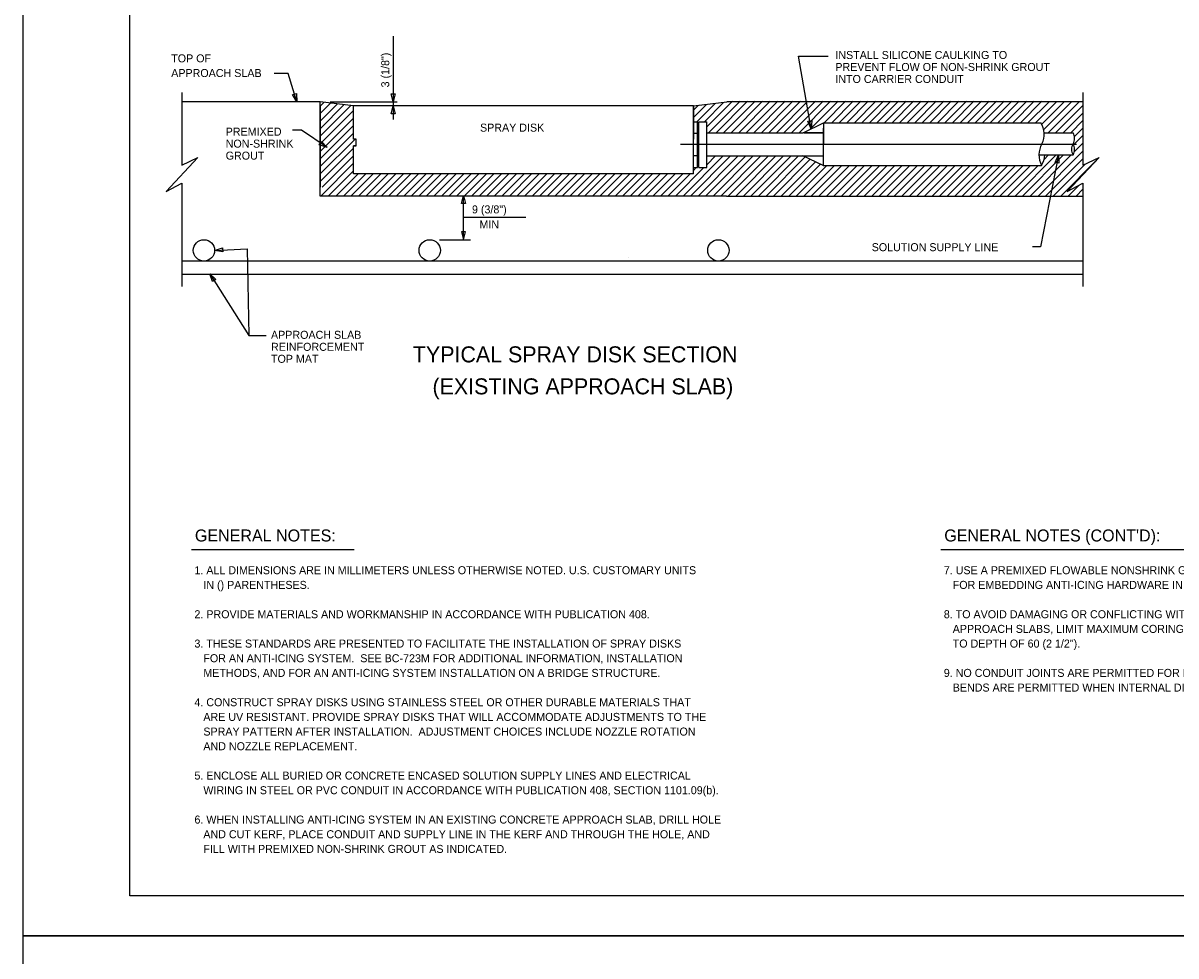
# Model space of a CAD drawing. Extents: x 3239 to 4230, y -4276 to -2494.
# Drawn here: x 3239 to 3671.4, y -3095.8 to -2746 of the extents above; entities that cross this region are included whole.
import ezdxf

# ---------------------------------------------------------------- set-up
doc = ezdxf.new("R2010")
doc.units = 0
doc.layers.add('2', color=7, linetype='Continuous')
doc.layers.add('PLT-BNDY', color=7, linetype='Continuous')

msp = doc.modelspace()

# ---------------------------------------------------------------- linework, layer by layer
at = {"layer": '2'}
for p, q in [((3279.03, -3073.29), (3279.03, -2509.29)), ((3377.84, -2750.85), (3377.84, -2782.13)), ((3338.44, -2764.84), (3333.2, -2764.84)), ((3341.71, -2775.45), (3338.44, -2764.84)), ((3298.57, -2772.06), (3298.57, -2799.29)), ((3350.43, -2775.45), (3298.57, -2775.45)), ((3362.93, -2776.95), (3350.43, -2775.45)), ((3350.43, -2810.82), (3350.43, -2775.45)), ((3354.22, -2775.45), (3379.34, -2775.45)), ((3490.43, -2776.95), (3502.93, -2775.45)), ((3495.43, -2784.92), (3505.05, -2775.29)), ((3496.07, -2787.11), (3507.88, -2775.29)), ((3498.9, -2787.11), (3510.71, -2775.29)), ((3501.73, -2787.11), (3513.54, -2775.29)), ((3636.47, -2775.45), (3502.93, -2775.45)), ((3504.56, -2787.11), (3516.37, -2775.29)), ((3507.39, -2787.11), (3519.2, -2775.29)), ((3510.22, -2787.11), (3522.03, -2775.29)), ((3513.05, -2787.11), (3524.86, -2775.29)), ((3515.88, -2787.11), (3527.69, -2775.29)), ((3518.71, -2787.11), (3530.52, -2775.29)), ((3521.54, -2787.11), (3533.35, -2775.29)), ((3524.37, -2787.11), (3536.18, -2775.29)), ((3527.2, -2787.11), (3539.01, -2775.29)), ((3530.03, -2787.11), (3541.84, -2775.29)), ((3534.18, -2785.79), (3544.67, -2775.29)), ((3539.44, -2783.35), (3547.5, -2775.29)), ((3542.27, -2783.35), (3550.33, -2775.29)), ((3545.1, -2783.35), (3553.16, -2775.29)), ((3547.93, -2783.35), (3555.99, -2775.29)), ((3550.76, -2783.35), (3558.82, -2775.29)), ((3553.59, -2783.35), (3561.65, -2775.29)), ((3556.42, -2783.35), (3564.48, -2775.29)), ((3559.25, -2783.35), (3567.31, -2775.29)), ((3562.08, -2783.35), (3570.14, -2775.29)), ((3564.91, -2783.35), (3572.97, -2775.29)), ((3567.74, -2783.35), (3575.8, -2775.29)), ((3570.57, -2783.35), (3578.63, -2775.29)), ((3573.4, -2783.35), (3581.46, -2775.29)), ((3576.23, -2783.35), (3584.29, -2775.29)), ((3579.06, -2783.35), (3587.12, -2775.29)), ((3581.89, -2783.35), (3589.95, -2775.29)), ((3584.72, -2783.35), (3592.78, -2775.29)), ((3587.55, -2783.35), (3595.61, -2775.29)), ((3590.38, -2783.35), (3598.44, -2775.29)), ((3593.21, -2783.35), (3601.27, -2775.29)), ((3596.04, -2783.35), (3604.1, -2775.29)), ((3598.87, -2783.35), (3606.93, -2775.29)), ((3601.7, -2783.35), (3609.76, -2775.29)), ((3604.53, -2783.35), (3612.59, -2775.29)), ((3607.36, -2783.35), (3615.42, -2775.29)), ((3610.19, -2783.35), (3618.25, -2775.29)), ((3613.02, -2783.35), (3621.08, -2775.29)), ((3615.85, -2783.35), (3623.76, -2775.45)), ((3618.68, -2783.35), (3626.59, -2775.45)), ((3621.02, -2783.84), (3629.42, -2775.45)), ((3621.79, -2785.89), (3632.24, -2775.45)), ((3623.4, -2787.12), (3635.07, -2775.45)), ((3636.47, -2772.06), (3636.47, -2799.29)), ((3350.43, -2777.1), (3351.9, -2775.62)), ((3350.43, -2779.93), (3354.43, -2775.93)), ((3350.43, -2782.75), (3356.95, -2776.23)), ((3350.43, -2785.58), (3359.48, -2776.53)), ((3350.43, -2788.41), (3362, -2776.83)), ((3350.43, -2776.95), (3350.43, -2807.45)), ((3350.43, -2791.24), (3362.93, -2778.74)), ((3362.93, -2789.45), (3362.93, -2776.95)), ((3362.93, -2789.45), (3362.93, -2776.95)), ((3490.43, -2776.95), (3362.93, -2776.95)), ((3490.43, -2781.43), (3495.3, -2776.55)), ((3490.43, -2778.58), (3492.28, -2776.72)), ((3490.43, -2789.45), (3490.43, -2776.95)), ((3490.43, -2776.95), (3490.43, -2789.45)), ((3491.74, -2782.95), (3498.52, -2776.16)), ((3494.57, -2782.95), (3501.74, -2775.78)), ((3626.23, -2787.12), (3636.47, -2776.87)), ((3629.05, -2787.12), (3636.47, -2779.7)), ((3350.43, -2794.07), (3362.93, -2781.57)), ((3490.43, -2782.95), (3491.92, -2782.95)), ((3491.92, -2800.19), (3491.92, -2782.95)), ((3492.42, -2800.19), (3492.42, -2782.95)), ((3492.42, -2782.95), (3495.43, -2782.95)), ((3495.43, -2800.19), (3495.43, -2782.95)), ((3539.13, -2783.57), (3539.12, -2799.32)), ((3539.13, -2783.35), (3620.73, -2783.35)), ((3631.88, -2787.12), (3636.47, -2782.53)), ((3343.4, -2786.1), (3340.03, -2786.1)), ((3353.01, -2792.68), (3343.4, -2786.1)), ((3350.43, -2796.9), (3362.93, -2784.4)), ((3350.43, -2799.72), (3362.93, -2787.22)), ((3490.43, -2787.3), (3491.92, -2787.3)), ((3495.43, -2797.45), (3495.43, -2785.45)), ((3495.43, -2787.11), (3531.52, -2787.11)), ((3531.92, -2787.11), (3539.12, -2787.11)), ((3539.12, -2787.11), (3539.12, -2795.78)), ((3539.14, -2791.89), (3539.13, -2788.2)), ((3621.97, -2787.12), (3632.77, -2787.12)), ((3632.98, -2791.68), (3636.47, -2788.18)), ((3633.28, -2788.55), (3636.47, -2785.35)), ((3350.43, -2802.55), (3363.53, -2789.45)), ((3363.93, -2789.45), (3362.93, -2789.45)), ((3363.93, -2789.45), (3362.93, -2789.45)), ((3363.93, -2791.95), (3362.93, -2791.95)), ((3362.93, -2802.45), (3362.93, -2791.95)), ((3362.93, -2795.95), (3362.93, -2791.95)), ((3362.93, -2791.95), (3363.93, -2791.95)), ((3363.93, -2791.95), (3363.93, -2789.45)), ((3363.93, -2791.95), (3363.93, -2789.45)), ((3608.55, -2791.45), (3485.58, -2791.45)), ((3490.43, -2802.45), (3490.43, -2789.45)), ((3634.08, -2791.45), (3608.55, -2791.45)), ((3633.23, -2794.25), (3636.47, -2791.01)), ((3304.6, -2796.39), (3292.7, -2809.17)), ((3298.57, -2799.29), (3304.6, -2796.39)), ((3350.43, -2805.38), (3362.93, -2792.88)), ((3351.19, -2807.45), (3362.69, -2795.95)), ((3486.51, -2810.82), (3501.54, -2795.78)), ((3489.34, -2810.82), (3504.37, -2795.78)), ((3490.43, -2795.6), (3491.92, -2795.6)), ((3492.17, -2810.82), (3507.2, -2795.78)), ((3495, -2810.82), (3510.03, -2795.78)), ((3495.43, -2795.78), (3531.49, -2795.78)), ((3495.43, -2799.07), (3498.71, -2795.78)), ((3497.83, -2810.82), (3512.86, -2795.78)), ((3500.66, -2810.82), (3515.69, -2795.78)), ((3503.49, -2810.82), (3518.52, -2795.78)), ((3506.32, -2810.82), (3521.35, -2795.78)), ((3509.15, -2810.82), (3524.18, -2795.78)), ((3511.98, -2810.82), (3527.01, -2795.78)), ((3514.81, -2810.82), (3529.84, -2795.78)), ((3517.64, -2810.82), (3532.3, -2796.16)), ((3520.47, -2810.82), (3534.23, -2797.05)), ((3531.92, -2795.78), (3539.12, -2795.78)), ((3611.01, -2810.82), (3626.4, -2795.43)), ((3613.84, -2810.82), (3629.23, -2795.43)), ((3616.67, -2810.82), (3632.05, -2795.43)), ((3619.65, -2810.82), (3636.47, -2793.99)), ((3619.96, -2795.43), (3632.77, -2795.43)), ((3621.9, -2797.1), (3623.57, -2795.43)), ((3622.47, -2810.82), (3636.47, -2796.82)), ((3628.13, -2810.82), (3641.79, -2797.16)), ((3642.51, -2796.39), (3630.6, -2809.17)), ((3636.47, -2799.29), (3642.51, -2796.39)), ((3350.65, -2810.82), (3362.93, -2798.54)), ((3353.48, -2810.82), (3362.93, -2801.37)), ((3483.68, -2810.82), (3494.3, -2800.19)), ((3490.43, -2800.19), (3491.92, -2800.19)), ((3490.43, -2801.24), (3491.47, -2800.19)), ((3492.42, -2800.19), (3495.43, -2800.19)), ((3523.3, -2810.82), (3536.16, -2797.95)), ((3526.13, -2810.82), (3538.09, -2798.85)), ((3528.96, -2810.82), (3540.45, -2799.32)), ((3531.79, -2810.82), (3543.28, -2799.32)), ((3534.62, -2810.82), (3546.11, -2799.32)), ((3537.45, -2810.82), (3548.94, -2799.32)), ((3539.12, -2799.32), (3620.98, -2799.32)), ((3540.28, -2810.82), (3551.77, -2799.32)), ((3543.11, -2810.82), (3554.6, -2799.32)), ((3545.94, -2810.82), (3557.43, -2799.32)), ((3548.77, -2810.82), (3560.26, -2799.32)), ((3551.6, -2810.82), (3563.09, -2799.32)), ((3554.43, -2810.82), (3565.92, -2799.32)), ((3557.26, -2810.82), (3568.75, -2799.32)), ((3560.09, -2810.82), (3571.58, -2799.32)), ((3562.92, -2810.82), (3574.41, -2799.32)), ((3565.75, -2810.82), (3577.24, -2799.32)), ((3568.58, -2810.82), (3580.07, -2799.32)), ((3571.41, -2810.82), (3582.9, -2799.32)), ((3574.24, -2810.82), (3585.73, -2799.32)), ((3577.07, -2810.82), (3588.56, -2799.32)), ((3579.9, -2810.82), (3591.39, -2799.32)), ((3582.73, -2810.82), (3594.22, -2799.32)), ((3585.56, -2810.82), (3597.05, -2799.32)), ((3588.39, -2810.82), (3599.88, -2799.32)), ((3591.22, -2810.82), (3602.71, -2799.32)), ((3594.04, -2810.82), (3605.54, -2799.32)), ((3596.87, -2810.82), (3608.37, -2799.32)), ((3599.7, -2810.82), (3611.19, -2799.32)), ((3602.53, -2810.82), (3614.02, -2799.32)), ((3605.35, -2810.82), (3616.85, -2799.32)), ((3608.18, -2810.82), (3619.67, -2799.32)), ((3625.3, -2810.82), (3637.16, -2798.96)), ((3356.31, -2810.82), (3364.68, -2802.45)), ((3359.13, -2810.82), (3367.51, -2802.45)), ((3361.96, -2810.82), (3370.33, -2802.45)), ((3490.43, -2802.45), (3362.93, -2802.45)), ((3364.79, -2810.82), (3373.16, -2802.45)), ((3367.62, -2810.82), (3375.99, -2802.45)), ((3370.45, -2810.82), (3378.82, -2802.45)), ((3373.28, -2810.82), (3381.65, -2802.45)), ((3376.1, -2810.82), (3384.48, -2802.45)), ((3378.93, -2810.82), (3387.3, -2802.45)), ((3381.76, -2810.82), (3390.13, -2802.45)), ((3384.59, -2810.82), (3392.96, -2802.45)), ((3387.42, -2810.82), (3395.79, -2802.45)), ((3390.25, -2810.82), (3398.62, -2802.45)), ((3393.08, -2810.82), (3401.45, -2802.45)), ((3395.9, -2810.82), (3404.27, -2802.45)), ((3398.73, -2810.82), (3407.1, -2802.45)), ((3423.57, -2802.45), (3399.93, -2802.45)), ((3401.56, -2810.82), (3409.93, -2802.45)), ((3404.39, -2810.82), (3412.76, -2802.45)), ((3407.22, -2810.82), (3415.59, -2802.45)), ((3410.05, -2810.82), (3418.42, -2802.45)), ((3412.87, -2810.82), (3421.25, -2802.45)), ((3415.7, -2810.82), (3424.07, -2802.45)), ((3418.54, -2810.82), (3426.91, -2802.45)), ((3421.38, -2810.82), (3429.75, -2802.45)), ((3424.22, -2810.82), (3432.59, -2802.45)), ((3427.06, -2810.82), (3435.43, -2802.45)), ((3429.89, -2810.82), (3438.26, -2802.45)), ((3432.73, -2810.82), (3441.1, -2802.45)), ((3435.57, -2810.82), (3443.94, -2802.45)), ((3438.41, -2810.82), (3446.78, -2802.45)), ((3441.25, -2810.82), (3449.62, -2802.45)), ((3444.08, -2810.82), (3452.45, -2802.45)), ((3446.92, -2810.82), (3455.29, -2802.45)), ((3449.52, -2810.82), (3457.89, -2802.45)), ((3452.52, -2810.82), (3460.9, -2802.45)), ((3455.35, -2810.82), (3463.72, -2802.45)), ((3458.18, -2810.82), (3466.55, -2802.45)), ((3461.04, -2810.82), (3469.41, -2802.45)), ((3463.87, -2810.82), (3472.24, -2802.45)), ((3466.7, -2810.82), (3475.07, -2802.45)), ((3469.53, -2810.82), (3477.9, -2802.45)), ((3472.36, -2810.82), (3480.73, -2802.45)), ((3475.19, -2810.82), (3483.56, -2802.45)), ((3478.02, -2810.82), (3486.39, -2802.45)), ((3480.85, -2810.82), (3489.22, -2802.45)), ((3292.7, -2809.17), (3298.57, -2806.04)), ((3298.57, -2806.04), (3298.57, -2844.75)), ((3630.6, -2809.17), (3636.47, -2806.04)), ((3630.96, -2810.82), (3634.9, -2806.88)), ((3633.88, -2810.82), (3636.47, -2808.22)), ((3636.47, -2806.04), (3636.47, -2844.75)), ((3502.83, -2810.82), (3350.43, -2810.82)), ((3404.23, -2827.22), (3404.23, -2810.67)), ((3502.83, -2810.82), (3636.47, -2810.82)), ((3404.23, -2818.73), (3427.51, -2818.73)), ((3395.19, -2827.22), (3406.86, -2827.22)), ((3636.47, -2835.24), (3298.57, -2835.24)), ((3636.47, -2840.24), (3298.57, -2840.24)), ((3302.22, -2943.37), (3363.24, -2943.37)), ((3583.23, -2943.37), (3687.39, -2943.37)), ((4065.03, -3073.29), (3279.03, -3073.29))]:
    msp.add_line(p, q, dxfattribs=at)
for points in [[(3534.56, -2785.6), (3529.77, -2758.37), (3540.95, -2758.37)], [(3627.34, -2795.43), (3620.62, -2829.85), (3617.52, -2829.85)], [(3310.86, -2831.22), (3323.11, -2830.57), (3323.66, -2863.08)], [(3309.04, -2839.95), (3323.66, -2863.08), (3323.66, -2863.08), (3330.13, -2863.08)]]:
    msp.add_lwpolyline(points, dxfattribs=at)
for points in [[(3341.54, -2772.36), (3341.71, -2775.45), (3340.11, -2772.8)], [(3378.59, -2772.45), (3377.84, -2775.45), (3377.09, -2772.45)], [(3377.09, -2779.95), (3377.84, -2776.95), (3378.59, -2779.95)], [(3539.13, -2783.32), (3539.12, -2787.11), (3531.52, -2787.11)], [(3534.78, -2782.51), (3534.56, -2785.6), (3533.3, -2782.77)], [(3350.96, -2790.37), (3353.01, -2792.68), (3350.11, -2791.61)], [(3531.49, -2795.78), (3539.12, -2795.78), (3539.12, -2799.32)], [(3626.03, -2798.23), (3627.34, -2795.43), (3627.5, -2798.52)], [(3403.48, -2813.67), (3404.23, -2810.67), (3404.98, -2813.67)], [(3403.48, -2824.22), (3404.23, -2827.22), (3404.98, -2824.22)], [(3313.89, -2831.81), (3310.86, -2831.22), (3313.81, -2830.31)], [(3310.01, -2842.89), (3309.04, -2839.95), (3311.28, -2842.09)]]:
    msp.add_lwpolyline(points, close=True, dxfattribs=at)
for centre in [(3306.86, -2831.22), (3391.53, -2831.22), (3499.78, -2831.22)]:
    msp.add_circle(centre, 4, dxfattribs=at)
for centre, radius, start, end in [((3614.06, -2787.64), 7.93, 332.7154, 32.7154), ((3629.17, -2789.19), 4.16, 330, 30), ((3628.04, -2795.42), 8.08, 149.1201, 209.1201), ((3636.37, -2793.35), 4.16, 150, 210), ((3629.17, -2793.35), 4.16, 330, 30), ((3614.05, -2795.2), 8.08, 329.1201, 358.4019), ((3445.88, -2833.73), 20, 0, 2.777777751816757e-06)]:
    msp.add_arc(centre, radius, start, end, dxfattribs=at)
at = {"layer": 'PLT-BNDY'}
for points in [[(3239.03, -2494.29), (4080.03, -2494.29), (4080.03, -3088.29), (3239.03, -3088.29)], [(3239.03, -3088.29), (4080.03, -3088.29), (4080.03, -3682.29), (3239.03, -3682.29)]]:
    msp.add_lwpolyline(points, close=True, dxfattribs=at)

# ---------------------------------------------------------------- texts
at = {"layer": '2'}
for s, height, p in [('TOP OF', 3, (3294.59, -2760.7)), ('INSTALL SILICONE CAULKING TO ', 3, (3543.63, -2759.43)), ('PREVENT FLOW OF NON-SHRINK GROUT', 3, (3543.63, -2763.93)), ('APPROACH SLAB', 3, (3294.59, -2766.2)), ('INTO CARRIER CONDUIT', 3, (3543.63, -2768.43)), ('SPRAY DISK', 3, (3410.39, -2786.68)), ('PREMIXED', 3, (3315.01, -2788.18)), ('NON-SHRINK', 3, (3315.01, -2792.68)), ('GROUT', 3, (3315.01, -2797.18)), ('9 (3/8")', 3, (3407.37, -2817.34)), ('MIN ', 3, (3410.17, -2822.98)), ('SOLUTION SUPPLY LINE', 3, (3557.26, -2831.51)), ('APPROACH SLAB', 3, (3332, -2864.37)), ('REINFORCEMENT', 3, (3332, -2868.87)), ('TOP MAT', 3, (3332, -2873.37)), ('TYPICAL SPRAY DISK SECTION', 6, (3385.21, -2873.2)), ('(EXISTING APPROACH SLAB)', 6, (3392.56, -2885.2)), ('GENERAL NOTES:', 4.5, (3303.47, -2940.37)), ("GENERAL NOTES (CONT'D):", 4.5, (3584.48, -2940.37)), (' 1. ALL DIMENSIONS ARE IN MILLIMETERS UNLESS OTHERWISE NOTED. U.S. CUSTOMARY UNITS ', 3, (3302.18, -2952.65)), (' 7. USE A PREMIXED FLOWABLE NONSHRINK GROUT AS PER PUBLICATION 408, SECTION 1080.2(c),  ', 3, (3583.19, -2952.65)), ('    IN () PARENTHESES.', 3, (3302.18, -2958.15)), ('    FOR EMBEDDING ANTI-ICING HARDWARE IN CONCRETE.', 3, (3583.19, -2958.15)), (' 2. PROVIDE MATERIALS AND WORKMANSHIP IN ACCORDANCE WITH PUBLICATION 408.', 3, (3302.18, -2969.15)), (' 8. TO AVOID DAMAGING OR CONFLICTING WITH REINFORCING STEEL IN EXISTING CONCRETE ', 3, (3583.19, -2969.15)), ('    APPROACH SLABS, LIMIT MAXIMUM CORING AND SAW CUTTING FOR SPRAY DISKS AND CONDUITS', 3, (3583.19, -2974.65)), (' 3. THESE STANDARDS ARE PRESENTED TO FACILITATE THE INSTALLATION OF SPRAY DISKS ', 3, (3302.18, -2980.15)), ('    TO DEPTH OF 60 (2 1/2").', 3, (3583.19, -2980.15)), ('    FOR AN ANTI-ICING SYSTEM.  SEE BC-723M FOR ADDITIONAL INFORMATION, INSTALLATION ', 3, (3302.18, -2985.65)), ('    METHODS, AND FOR AN ANTI-ICING SYSTEM INSTALLATION ON A BRIDGE STRUCTURE.', 3, (3302.18, -2991.15)), (' 9. NO CONDUIT JOINTS ARE PERMITTED FOR INSTALLATION IN EXISTING CONCRETE.  FIELD', 3, (3583.19, -2991.15)), ('    BENDS ARE PERMITTED WHEN INTERNAL DIAMETER IS MAINTAINED.', 3, (3583.19, -2996.65)), (' 4. CONSTRUCT SPRAY DISKS USING STAINLESS STEEL OR OTHER DURABLE MATERIALS THAT ', 3, (3302.18, -3002.15)), ('    ARE UV RESISTANT. PROVIDE SPRAY DISKS THAT WILL ACCOMMODATE ADJUSTMENTS TO THE ', 3, (3302.18, -3007.65)), ('    SPRAY PATTERN AFTER INSTALLATION.  ADJUSTMENT CHOICES INCLUDE NOZZLE ROTATION ', 3, (3302.18, -3013.15)), ('    AND NOZZLE REPLACEMENT.', 3, (3302.18, -3018.65)), (' 5. ENCLOSE ALL BURIED OR CONCRETE ENCASED SOLUTION SUPPLY LINES AND ELECTRICAL ', 3, (3302.18, -3029.65)), ('    WIRING IN STEEL OR PVC CONDUIT IN ACCORDANCE WITH PUBLICATION 408, SECTION 1101.09(b).', 3, (3302.18, -3035.15)), (' 6. WHEN INSTALLING ANTI-ICING SYSTEM IN AN EXISTING CONCRETE APPROACH SLAB, DRILL HOLE ', 3, (3302.18, -3046.15)), ('    AND CUT KERF, PLACE CONDUIT AND SUPPLY LINE IN THE KERF AND THROUGH THE HOLE, AND ', 3, (3302.18, -3051.65)), ('    FILL WITH PREMIXED NON-SHRINK GROUT AS INDICATED.', 3, (3302.18, -3057.15))]:
    msp.add_text(s, height=height, dxfattribs=at).set_placement(p)
msp.add_text('3 (1/8")', height=3, rotation=90, dxfattribs=at).set_placement((3376.34, -2770.09))

doc.saveas('drawing.dxf')
